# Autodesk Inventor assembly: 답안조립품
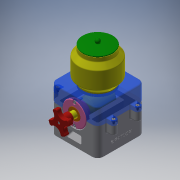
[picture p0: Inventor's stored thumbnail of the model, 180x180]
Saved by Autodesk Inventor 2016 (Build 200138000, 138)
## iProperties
Created: 2022-03
Part Number: 답안조립품
Material: 일반
Document SubType Name: Weldment
Designer: CAD01
Weld Material: Welded Aluminum-6061
Author: CAD01
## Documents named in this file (11)
- C:\Users\CAD01\Desktop\720306V1002\답안조립품.iam
- C:\Users\CAD01\Desktop\720306V1002\본체.ipt
- C:\Users\CAD01\Desktop\720306V1002\핸들축.ipt
- C:\Users\CAD01\Desktop\720306V1002\핸들.ipt
- C:\Users\CAD01\Desktop\720306V1002\볼트 M3x12.ipt
- C:\Users\CAD01\Desktop\720306V1002\앞커버.ipt
- C:\Users\CAD01\Desktop\720306V1002\베어링 부시.ipt
- C:\Users\CAD01\Desktop\720306V1002\볼트 M4x12.ipt
- C:\Users\CAD01\Desktop\720306V1002\본체커버.ipt
- C:\Users\CAD01\Desktop\720306V1002\용기.ipt
- C:\Users\CAD01\Desktop\720306V1002\용기캡.ipt
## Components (2 placed, 2 different names)
1. 핸들축:2
2. 핸들:1
